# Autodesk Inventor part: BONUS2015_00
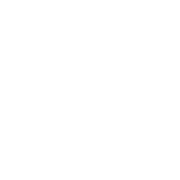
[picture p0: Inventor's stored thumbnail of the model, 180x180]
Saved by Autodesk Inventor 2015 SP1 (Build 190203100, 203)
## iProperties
Created: 2015-05
Part Number: BONUS2015_00
Material: Generisch
Document SubType Name: Modeling
Density: 1 g/cm^3
Appearance: Vorgabe
xx: 00
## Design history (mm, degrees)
